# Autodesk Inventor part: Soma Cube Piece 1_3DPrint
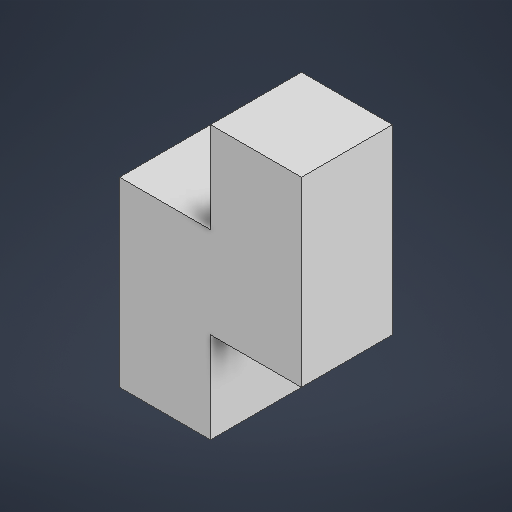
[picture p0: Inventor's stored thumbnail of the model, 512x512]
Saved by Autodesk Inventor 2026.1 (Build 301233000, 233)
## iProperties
Created: 2025-12
Part Number: Soma Cube Piece 1_3DPrint
Material: Generic
Document SubType Name: Modeling
Designer: egberbos000
Density: 1 g/cm^3
Appearance: Default
Author: egberbos000
Part Number: Soma Cube Piece 1
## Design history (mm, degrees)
sketch "Sketch1"
  geometry: L1 (0, 0)-(25.4, 0); L2 (25.4, 0)-(25.4, 50.8); L3 (25.4, 50.8)-(0, 50.8); L4 (0, 50.8)-(0, 0); L5 (25.4, 25.4)-(50.8, 25.4); L6 (50.8, 25.4)-(50.8, 76.2); L7 (50.8, 76.2)-(25.4, 76.2); L8 (25.4, 76.2)-(25.4, 25.4); 1 further point
  constraints: 16 end point, 4 parallel, 2 horizontal, 2 perpendicular, 1 midpoint
  dimensions: "d0" = 25.4 distance of L2.end L3.end; "d1" = 50.8 distance of L1.end L2.end; "d2" = 25.4 distance of L6.end L7.end; "d3" = 50.8 distance of L5.end L6.end
extrude "Extrusion1" new body sketch "Sketch1" distance "d4" = 25.4; taper "d5" = 0 deg
body "Solid1"
